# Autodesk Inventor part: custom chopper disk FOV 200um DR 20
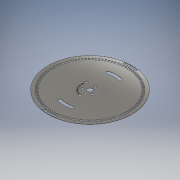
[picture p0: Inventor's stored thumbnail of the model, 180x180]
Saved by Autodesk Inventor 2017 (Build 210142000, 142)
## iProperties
Created: 2016-09
Part Number: custom chopper disk FOV 200um DR 20
Material: Generic
Document SubType Name: Modeling
Designer: Radek
Density: 1 g/cm^3
Appearance: Mirror
Author: Radek
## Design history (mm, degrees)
workplane "Work Plane1"
sketch "Sketch1"
  geometry: L1 (-46.781, 4.422)-(-44.253, 4.183) reference; L2 (-44.362, 2.791)-(-46.897, 2.951) reference; L3 (-46.411, 7.351)-(-43.903, 6.954) reference; L4 (-44.099, 5.571)-(-46.619, 5.889) reference; L5 (-45.858, 10.251)-(-43.38, 9.696) reference; L6 (-43.663, 8.329)-(-46.158, 8.805) reference; L7 (-45.124, 13.11)-(-42.685, 12.401) reference; L8 (-43.054, 11.054)-(-45.514, 11.686) reference; L9 (-44.212, 15.917)-(-41.822, 15.057) reference; L10 (-42.274, 13.736)-(-44.69, 14.521) reference; L11 (-43.125, 18.662)-(-40.794, 17.653) reference; L12 (-41.329, 16.363)-(-43.69, 17.298) reference; L13 (-41.868, 21.333)-(-39.605, 20.18) reference; L14 (-40.22, 18.926)-(-42.518, 20.007) reference; L15 (-40.446, 23.92)-(-38.26, 22.627) reference; L16 (-38.952, 21.414)-(-41.178, 22.638) reference; L17 (-38.865, 26.412)-(-36.764, 24.985) reference; L18 (-37.53, 23.818)-(-39.675, 25.179) reference; L19 (-37.129, 28.801)-(-35.122, 27.244) reference; L20 (-35.961, 26.127)-(-38.016, 27.62) reference; L21 (-35.248, 31.075)-(-33.342, 29.395) reference; L22 (-34.249, 28.333)-(-36.206, 29.953) reference; L23 (-33.227, 33.227)-(-31.431, 31.431) reference; L24 (-32.403, 30.428)-(-34.254, 32.167) reference; L25 (-31.075, 35.248)-(-29.395, 33.342) reference; L26 (-30.428, 32.403)-(-32.167, 34.254) reference; L27 (-28.801, 37.129)-(-27.244, 35.122) reference; L28 (-28.333, 34.249)-(-29.953, 36.206) reference; L29 (-26.412, 38.865)-(-24.985, 36.764) reference; L30 (-26.127, 35.961)-(-27.62, 38.016) reference; L31 (-23.92, 40.446)-(-22.627, 38.26) reference; L32 (-23.818, 37.53)-(-25.179, 39.675) reference; L33 (-21.333, 41.868)-(-20.18, 39.605) reference; L34 (-21.414, 38.952)-(-22.638, 41.178) reference; L35 (-18.662, 43.125)-(-17.653, 40.794) reference; L36 (-18.926, 40.22)-(-20.007, 42.518) reference; L37 (-15.917, 44.212)-(-15.057, 41.822) reference; L38 (-16.363, 41.329)-(-17.298, 43.69) reference; L39 (-13.11, 45.124)-(-12.401, 42.685) reference; L40 (-13.736, 42.274)-(-14.521, 44.69) reference; L41 (-10.251, 45.858)-(-9.696, 43.38) reference; L42 (-11.054, 43.054)-(-11.686, 45.514) reference; L43 (-7.351, 46.411)-(-6.954, 43.903) reference; L44 (-8.329, 43.663)-(-8.805, 46.158) reference; L45 (-4.422, 46.781)-(-4.183, 44.253) reference; L46 (-5.571, 44.099)-(-5.889, 46.619) reference; L47 (-1.476, 46.967)-(-1.396, 44.428) reference; L48 (-2.791, 44.362)-(-2.951, 46.897) reference; L49 (1.476, 46.967)-(1.396, 44.428) reference; L50 (0, 44.45)-(0, 46.99) reference; L51 (4.422, 46.781)-(4.183, 44.253) reference; L52 (2.791, 44.362)-(2.951, 46.897) reference; L53 (7.351, 46.411)-(6.954, 43.903) reference; L54 (5.571, 44.099)-(5.889, 46.619) reference; L55 (10.251, 45.858)-(9.696, 43.38) reference; L56 (8.329, 43.663)-(8.805, 46.158) reference; L57 (13.11, 45.124)-(12.401, 42.685) reference; L58 (11.054, 43.054)-(11.686, 45.514) reference; L59 (15.917, 44.212)-(15.057, 41.822) reference; L60 (13.736, 42.274)-(14.521, 44.69) reference; L61 (18.662, 43.125)-(17.653, 40.794) reference; L62 (16.363, 41.329)-(17.298, 43.69) reference; L63 (21.333, 41.868)-(20.18, 39.605) reference; L64 (18.926, 40.22)-(20.007, 42.518) reference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; C1 r 50.8 at (0, 0) reference; C2 r 2.984 at (0, 0) reference; C3 r 1.524 at (0, 6.553) reference; C4 r 1.524 at (10.339, 5.969) reference; C5 r 2.984 at (0, 0) reference; C6 r 1.524 at (0, -11.938) reference; C7 r 1.524 at (-5.675, -3.277) reference; C8 r 1.524 at (-10.339, 5.969) reference; C9 r 1.524 at (5.675, -3.277) reference; C10 r 50.8 at (0, 0) reference; C11 r 1.524 at (-5.675, -3.277) reference; C12 r 1.524 at (-10.339, 5.969) reference; C13 r 1.524 at (0, 6.553) reference; C14 r 1.524 at (10.339, 5.969) reference; C15 r 1.524 at (5.675, -3.277) reference; C16 r 1.524 at (0, -11.938) reference; C17 r 2.984 at (0, 0) reference; A1 r 17.081 centre (0, 0) between (0, -17.081) and (17.081, 0) reference; A2 r 17.081 centre (0, 0) between (0, 17.081) and (-17.081, 0) reference; A3 r 43.18 centre (0, 0) between (0, 43.18) and (-43.18, 0) reference; A4 r 43.18 centre (0, 0) between (0, -43.18) and (43.18, 0) reference; A5 r 44.45 centre (0, 0) between (-44.253, 4.183) and (-44.362, 2.791) reference; A6 r 46.99 centre (0, 0) between (-46.781, 4.422) and (-46.897, 2.951) reference; A7 r 44.45 centre (0, 0) between (-43.903, 6.954) and (-44.099, 5.571) reference; A8 r 46.99 centre (0, 0) between (-46.411, 7.351) and (-46.619, 5.889) reference; A9 r 44.45 centre (0, 0) between (-43.38, 9.696) and (-43.663, 8.329) reference; A10 r 46.99 centre (0, 0) between (-45.858, 10.251) and (-46.158, 8.805) reference; A11 r 44.45 centre (0, 0) between (-42.685, 12.401) and (-43.054, 11.054) reference; A12 r 46.99 centre (0, 0) between (-45.124, 13.11) and (-45.514, 11.686) reference; A13 r 44.45 centre (0, 0) between (-41.822, 15.057) and (-42.274, 13.736) reference; A14 r 46.99 centre (0, 0) between (-44.212, 15.917) and (-44.69, 14.521) reference; A15 r 44.45 centre (0, 0) between (-40.794, 17.653) and (-41.329, 16.363) reference; A16 r 46.99 centre (0, 0) between (-43.125, 18.662) and (-43.69, 17.298) reference; A17 r 44.45 centre (0, 0) between (-39.605, 20.18) and (-40.22, 18.926) reference; A18 r 46.99 centre (0, 0) between (-41.868, 21.333) and (-42.518, 20.007) reference; A19 r 44.45 centre (0, 0) between (-38.26, 22.627) and (-38.952, 21.414) reference; A20 r 46.99 centre (0, 0) between (-40.446, 23.92) and (-41.178, 22.638) reference; A21 r 44.45 centre (0, 0) between (-36.764, 24.985) and (-37.53, 23.818) reference; A22 r 46.99 centre (0, 0) between (-38.865, 26.412) and (-39.675, 25.179) reference; A23 r 44.45 centre (0, 0) between (-35.122, 27.244) and (-35.961, 26.127) reference; A24 r 46.99 centre (0, 0) between (-37.129, 28.801) and (-38.016, 27.62) reference; A25 r 44.45 centre (0, 0) between (-33.342, 29.395) and (-34.249, 28.333) reference; A26 r 46.99 centre (0, 0) between (-35.248, 31.075) and (-36.206, 29.953) reference; A27 r 44.45 centre (0, 0) between (-31.431, 31.431) and (-32.403, 30.428) reference; A28 r 46.99 centre (0, 0) between (-33.227, 33.227) and (-34.254, 32.167) reference; A29 r 44.45 centre (0, 0) between (-29.395, 33.342) and (-30.428, 32.403) reference; A30 r 46.99 centre (0, 0) between (-31.075, 35.248) and (-32.167, 34.254) reference; A31 r 44.45 centre (0, 0) between (-27.244, 35.122) and (-28.333, 34.249) reference; A32 r 46.99 centre (0, 0) between (-28.801, 37.129) and (-29.953, 36.206) reference; A33 r 44.45 centre (0, 0) between (-24.985, 36.764) and (-26.127, 35.961) reference; A34 r 46.99 centre (0, 0) between (-26.412, 38.865) and (-27.62, 38.016) reference; A35 r 44.45 centre (0, 0) between (-22.627, 38.26) and (-23.818, 37.53) reference; A36 r 46.99 centre (0, 0) between (-23.92, 40.446) and (-25.179, 39.675) reference; A37 r 44.45 centre (0, 0) between (-20.18, 39.605) and (-21.414, 38.952) reference; A38 r 46.99 centre (0, 0) between (-21.333, 41.868) and (-22.638, 41.178) reference; A39 r 44.45 centre (0, 0) between (-17.653, 40.794) and (-18.926, 40.22) reference; A40 r 46.99 centre (0, 0) between (-18.662, 43.125) and (-20.007, 42.518) reference; A41 r 44.45 centre (0, 0) between (-15.057, 41.822) and (-16.363, 41.329) reference; A42 r 46.99 centre (0, 0) between (-15.917, 44.212) and (-17.298, 43.69) reference; A43 r 44.45 centre (0, 0) between (-12.401, 42.685) and (-13.736, 42.274) reference; A44 r 46.99 centre (0, 0) between (-13.11, 45.124) and (-14.521, 44.69) reference; A45 r 44.45 centre (0, 0) between (-9.696, 43.38) and (-11.054, 43.054) reference; A46 r 46.99 centre (0, 0) between (-10.251, 45.858) and (-11.686, 45.514) reference; A47 r 44.45 centre (0, 0) between (-6.954, 43.903) and (-8.329, 43.663) reference; A48 r 46.99 centre (0, 0) between (-7.351, 46.411) and (-8.805, 46.158) reference; A49 r 44.45 centre (0, 0) between (-4.183, 44.253) and (-5.571, 44.099) reference; A50 r 46.99 centre (0, 0) between (-4.422, 46.781) and (-5.889, 46.619) reference; A51 r 44.45 centre (0, 0) between (-1.396, 44.428) and (-2.791, 44.362) reference; A52 r 46.99 centre (0, 0) between (-1.476, 46.967) and (-2.951, 46.897) reference; A53 r 44.45 centre (0, 0) between (1.396, 44.428) and (0, 44.45) reference; A54 r 46.99 centre (0, 0) between (1.476, 46.967) and (0, 46.99) reference; A55 r 44.45 centre (0, 0) between (4.183, 44.253) and (2.791, 44.362) reference; A56 r 46.99 centre (0, 0) between (4.422, 46.781) and (2.951, 46.897) reference; A57 r 44.45 centre (0, 0) between (6.954, 43.903) and (5.571, 44.099) reference; A58 r 46.99 centre (0, 0) between (7.351, 46.411) and (5.889, 46.619) reference; A59 r 44.45 centre (0, 0) between (9.696, 43.38) and (8.329, 43.663) reference; A60 r 46.99 centre (0, 0) between (10.251, 45.858) and (8.805, 46.158) reference; A61 r 44.45 centre (0, 0) between (12.401, 42.685) and (11.054, 43.054) reference; A62 r 46.99 centre (0, 0) between (13.11, 45.124) and (11.686, 45.514) reference; A63 r 44.45 centre (0, 0) between (15.057, 41.822) and (13.736, 42.274) reference; A64 r 46.99 centre (0, 0) between (15.917, 44.212) and (14.521, 44.69) reference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; 1 further point
  constraints: 8 end point, 2 collinear, 1 parallel
extrude "Extrusion2" new body sketch "Sketch1" distance "d2" = 0.254; taper "d3" = 0 deg
sketch "Sketch2"
  geometry: L1 (-46.781, 4.422)-(-44.253, 4.183) reference; L2 (-44.362, 2.791)-(-46.897, 2.951) reference; L3 (-46.411, 7.351)-(-43.903, 6.954) reference; L4 (-44.099, 5.571)-(-46.619, 5.889) reference; L5 (-45.858, 10.251)-(-43.38, 9.696) reference; L6 (-43.663, 8.329)-(-46.158, 8.805) reference; L7 (-45.124, 13.11)-(-42.685, 12.401) reference; L8 (-43.054, 11.054)-(-45.514, 11.686) reference; L9 (-44.212, 15.917)-(-41.822, 15.057) reference; L10 (-42.274, 13.736)-(-44.69, 14.521) reference; L11 (-43.125, 18.662)-(-40.794, 17.653) reference; L12 (-41.329, 16.363)-(-43.69, 17.298) reference; L13 (-41.868, 21.333)-(-39.605, 20.18) reference; L14 (-40.22, 18.926)-(-42.518, 20.007) reference; L15 (-40.446, 23.92)-(-38.26, 22.627) reference; L16 (-38.952, 21.414)-(-41.178, 22.638) reference; L17 (-38.865, 26.412)-(-36.764, 24.985) reference; L18 (-37.53, 23.818)-(-39.675, 25.179) reference; L19 (-37.129, 28.801)-(-35.122, 27.244) reference; L20 (-35.961, 26.127)-(-38.016, 27.62) reference; L21 (-35.248, 31.075)-(-33.342, 29.395) reference; L22 (-34.249, 28.333)-(-36.206, 29.953) reference; L23 (-33.227, 33.227)-(-31.431, 31.431) reference; L24 (-32.403, 30.428)-(-34.254, 32.167) reference; L25 (-31.075, 35.248)-(-29.395, 33.342) reference; L26 (-30.428, 32.403)-(-32.167, 34.254) reference; L27 (-28.801, 37.129)-(-27.244, 35.122) reference; L28 (-28.333, 34.249)-(-29.953, 36.206) reference; L29 (-26.412, 38.865)-(-24.985, 36.764) reference; L30 (-26.127, 35.961)-(-27.62, 38.016) reference; L31 (-23.92, 40.446)-(-22.627, 38.26) reference; L32 (-23.818, 37.53)-(-25.179, 39.675) reference; L33 (-21.333, 41.868)-(-20.18, 39.605) reference; L34 (-21.414, 38.952)-(-22.638, 41.178) reference; L35 (-18.662, 43.125)-(-17.653, 40.794) reference; L36 (-18.926, 40.22)-(-20.007, 42.518) reference; L37 (-15.917, 44.212)-(-15.057, 41.822) reference; L38 (-16.363, 41.329)-(-17.298, 43.69) reference; L39 (-13.11, 45.124)-(-12.401, 42.685) reference; L40 (-13.736, 42.274)-(-14.521, 44.69) reference; L41 (-10.251, 45.858)-(-9.696, 43.38) reference; L42 (-11.054, 43.054)-(-11.686, 45.514) reference; L43 (-7.351, 46.411)-(-6.954, 43.903) reference; L44 (-8.329, 43.663)-(-8.805, 46.158) reference; L45 (-4.422, 46.781)-(-4.183, 44.253) reference; L46 (-5.571, 44.099)-(-5.889, 46.619) reference; L47 (-1.476, 46.967)-(-1.396, 44.428) reference; L48 (-2.791, 44.362)-(-2.951, 46.897) reference; L49 (1.476, 46.967)-(1.396, 44.428) reference; L50 (0, 44.45)-(0, 46.99) reference; L51 (4.422, 46.781)-(4.183, 44.253) reference; L52 (2.791, 44.362)-(2.951, 46.897) reference; L53 (7.351, 46.411)-(6.954, 43.903) reference; L54 (5.571, 44.099)-(5.889, 46.619) reference; L55 (10.251, 45.858)-(9.696, 43.38) reference; L56 (8.329, 43.663)-(8.805, 46.158) reference; L57 (13.11, 45.124)-(12.401, 42.685) reference; L58 (11.054, 43.054)-(11.686, 45.514) reference; L59 (15.917, 44.212)-(15.057, 41.822) reference; L60 (13.736, 42.274)-(14.521, 44.69) reference; L61 (18.662, 43.125)-(17.653, 40.794) reference; L62 (16.363, 41.329)-(17.298, 43.69) reference; L63 (21.333, 41.868)-(20.18, 39.605) reference; L64 (18.926, 40.22)-(20.007, 42.518) reference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; C1 r 50.8 at (0, 0) reference; C2 r 1.524 at (-5.675, -3.277) reference; C3 r 1.524 at (-10.339, 5.969) reference; C4 r 1.524 at (0, 6.553) reference; C5 r 1.524 at (10.339, 5.969) reference; C6 r 1.524 at (5.675, -3.277) reference; C7 r 1.524 at (0, -11.938) reference; C8 r 2.984 at (0, 0) reference; A1 r 44.45 centre (0, 0) between (-44.253, 4.183) and (-44.362, 2.791) reference; A2 r 46.99 centre (0, 0) between (-46.781, 4.422) and (-46.897, 2.951) reference; A3 r 44.45 centre (0, 0) between (-43.903, 6.954) and (-44.099, 5.571) reference; A4 r 46.99 centre (0, 0) between (-46.411, 7.351) and (-46.619, 5.889) reference; A5 r 44.45 centre (0, 0) between (-43.38, 9.696) and (-43.663, 8.329) reference; A6 r 46.99 centre (0, 0) between (-45.858, 10.251) and (-46.158, 8.805) reference; A7 r 44.45 centre (0, 0) between (-42.685, 12.401) and (-43.054, 11.054) reference; A8 r 46.99 centre (0, 0) between (-45.124, 13.11) and (-45.514, 11.686) reference; A9 r 44.45 centre (0, 0) between (-41.822, 15.057) and (-42.274, 13.736) reference; A10 r 46.99 centre (0, 0) between (-44.212, 15.917) and (-44.69, 14.521) reference; A11 r 44.45 centre (0, 0) between (-40.794, 17.653) and (-41.329, 16.363) reference; A12 r 46.99 centre (0, 0) between (-43.125, 18.662) and (-43.69, 17.298) reference; A13 r 44.45 centre (0, 0) between (-39.605, 20.18) and (-40.22, 18.926) reference; A14 r 46.99 centre (0, 0) between (-41.868, 21.333) and (-42.518, 20.007) reference; A15 r 44.45 centre (0, 0) between (-38.26, 22.627) and (-38.952, 21.414) reference; A16 r 46.99 centre (0, 0) between (-40.446, 23.92) and (-41.178, 22.638) reference; A17 r 44.45 centre (0, 0) between (-36.764, 24.985) and (-37.53, 23.818) reference; A18 r 46.99 centre (0, 0) between (-38.865, 26.412) and (-39.675, 25.179) reference; A19 r 44.45 centre (0, 0) between (-35.122, 27.244) and (-35.961, 26.127) reference; A20 r 46.99 centre (0, 0) between (-37.129, 28.801) and (-38.016, 27.62) reference; A21 r 44.45 centre (0, 0) between (-33.342, 29.395) and (-34.249, 28.333) reference; A22 r 46.99 centre (0, 0) between (-35.248, 31.075) and (-36.206, 29.953) reference; A23 r 44.45 centre (0, 0) between (-31.431, 31.431) and (-32.403, 30.428) reference; A24 r 46.99 centre (0, 0) between (-33.227, 33.227) and (-34.254, 32.167) reference; A25 r 44.45 centre (0, 0) between (-29.395, 33.342) and (-30.428, 32.403) reference; A26 r 46.99 centre (0, 0) between (-31.075, 35.248) and (-32.167, 34.254) reference; A27 r 44.45 centre (0, 0) between (-27.244, 35.122) and (-28.333, 34.249) reference; A28 r 46.99 centre (0, 0) between (-28.801, 37.129) and (-29.953, 36.206) reference; A29 r 44.45 centre (0, 0) between (-24.985, 36.764) and (-26.127, 35.961) reference; A30 r 46.99 centre (0, 0) between (-26.412, 38.865) and (-27.62, 38.016) reference; A31 r 44.45 centre (0, 0) between (-22.627, 38.26) and (-23.818, 37.53) reference; A32 r 46.99 centre (0, 0) between (-23.92, 40.446) and (-25.179, 39.675) reference; A33 r 44.45 centre (0, 0) between (-20.18, 39.605) and (-21.414, 38.952) reference; A34 r 46.99 centre (0, 0) between (-21.333, 41.868) and (-22.638, 41.178) reference; A35 r 44.45 centre (0, 0) between (-17.653, 40.794) and (-18.926, 40.22) reference; A36 r 46.99 centre (0, 0) between (-18.662, 43.125) and (-20.007, 42.518) reference; A37 r 44.45 centre (0, 0) between (-15.057, 41.822) and (-16.363, 41.329) reference; A38 r 46.99 centre (0, 0) between (-15.917, 44.212) and (-17.298, 43.69) reference; A39 r 44.45 centre (0, 0) between (-12.401, 42.685) and (-13.736, 42.274) reference; A40 r 46.99 centre (0, 0) between (-13.11, 45.124) and (-14.521, 44.69) reference; A41 r 44.45 centre (0, 0) between (-9.696, 43.38) and (-11.054, 43.054) reference; A42 r 46.99 centre (0, 0) between (-10.251, 45.858) and (-11.686, 45.514) reference; A43 r 44.45 centre (0, 0) between (-6.954, 43.903) and (-8.329, 43.663) reference; A44 r 46.99 centre (0, 0) between (-7.351, 46.411) and (-8.805, 46.158) reference; A45 r 44.45 centre (0, 0) between (-4.183, 44.253) and (-5.571, 44.099) reference; A46 r 46.99 centre (0, 0) between (-4.422, 46.781) and (-5.889, 46.619) reference; A47 r 44.45 centre (0, 0) between (-1.396, 44.428) and (-2.791, 44.362) reference; A48 r 46.99 centre (0, 0) between (-1.476, 46.967) and (-2.951, 46.897) reference; A49 r 44.45 centre (0, 0) between (1.396, 44.428) and (0, 44.45) reference; A50 r 46.99 centre (0, 0) between (1.476, 46.967) and (0, 46.99) reference; A51 r 44.45 centre (0, 0) between (4.183, 44.253) and (2.791, 44.362) reference; A52 r 46.99 centre (0, 0) between (4.422, 46.781) and (2.951, 46.897) reference; A53 r 44.45 centre (0, 0) between (6.954, 43.903) and (5.571, 44.099) reference; A54 r 46.99 centre (0, 0) between (7.351, 46.411) and (5.889, 46.619) reference; A55 r 44.45 centre (0, 0) between (9.696, 43.38) and (8.329, 43.663) reference; A56 r 46.99 centre (0, 0) between (10.251, 45.858) and (8.805, 46.158) reference; A57 r 44.45 centre (0, 0) between (12.401, 42.685) and (11.054, 43.054) reference; A58 r 46.99 centre (0, 0) between (13.11, 45.124) and (11.686, 45.514) reference; A59 r 44.45 centre (0, 0) between (15.057, 41.822) and (13.736, 42.274) reference; A60 r 46.99 centre (0, 0) between (15.917, 44.212) and (14.521, 44.69) reference; A61 r 44.45 centre (0, 0) between (17.653, 40.794) and (16.363, 41.329) reference; A62 r 46.99 centre (0, 0) between (18.662, 43.125) and (17.298, 43.69) reference; A63 r 44.45 centre (0, 0) between (20.18, 39.605) and (18.926, 40.22) reference; A64 r 46.99 centre (0, 0) between (21.333, 41.868) and (20.007, 42.518) reference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; 1 further point
  constraints: 8 end point, 1 collinear
extrude "Extrusion3" cut sketch "Sketch2" stored distance "d4" = 0.254; taper "d5" = 0 deg
sketch "Sketch3" dims "d20" = 1.32222 (= 0.5 x holediameter), "d21" = 1.8699 (= 1.41421 x d20)
  geometry: L1 (-10.339, 5.969)-(10.339, 5.969); L2 (0, 0)-(50.8, 0); L3 (0, 44.45)-(0, 46.99) reference; L4 (0, 0)-(0, 50.8); L5 (0, 30)-(0, 28.13); L6 (0, 50.165)-(0, 48.26) reference; L7 (-48.26, 0)-(-50.165, 0) reference; L8 (0, 0)-(-3.071, -13.883); L9 (0, 50.8)-(0, 50.165); L10 (7.281, 27.172)-(8.273, 30.777); L11 (-7.281, 27.172)-(-8.273, 30.777); C1 r 2.984 at (0, 0) reference; C2 r 15.25 at (0, 0); C3 r 1.524 at (-10.339, 5.969) reference; C4 r 1.524 at (0, -11.938) reference; C5 r 1.524 at (10.339, 5.969) reference; C6 r 1.524 at (-5.675, -3.277) reference; C7 r 1.524 at (5.675, -3.277) reference; A1 r 50.8 centre (0, 0) between (50.8, 0) and (0, 50.8) reference; A2 r 48.26 centre (0, 0) between (0, 48.26) and (-48.26, 0) reference; A3 r 50.165 centre (0, 0) between (0, 50.165) and (-50.165, 0) reference; A4 r 50.165 centre (0, 0) between (-20.154, -45.939) and (22.037, -45.066); A5 r 48.26 centre (0, 0) between (-19.033, -44.348) and (20.956, -43.472); 3 further points; 3 other entities
  constraints: 16 end point, 8 point on circle, 3 centre point, 3 coincident, 2 vertical, 1 collinear, 1 horizontal, 1 parallel, 1 point on line, 1 vertical alignment, 19 other
  dimensions: "d9" = 30.5 diameter of C2; "d18" = 0 distance between parallel lines of L4 L5; "d19" = 30 distance of point (0, 0) L5.start (= offaxis); "d24" = 15 deg dimension on point (0, 0) L5.start point (-7.765, 28.978) (= 0.5 x angle); "d28" = 15 deg dimension on point (0, 0) point (7.765, 28.978) L5.start (= 0.5 x angle); "d32" = 0.635 distance of L4.end L6.start (derived)
extrude "Extrusion7" cut sketch "Sketch3" stored distance "d40" = 10; taper "d41" = 0 deg
sketch "Sketch4"
  geometry: L1 (-8.273, 30.777)-(-7.281, 27.172) reference; L2 (7.281, 27.172)-(8.273, 30.777) reference; L3 (8.273, 30.777)-(7.281, 27.172) reference; L4 (-7.281, 27.172)-(-8.273, 30.777) reference; L5 (-7.281, 27.172)-(-8.273, 30.777); L6 (7.281, 27.172)-(8.273, 30.777); C1 r 2.984 at (0, 0) reference; C2 r 50.8 at (0, 0) reference; A1 r 28.13 centre (0, 0) between (7.281, 27.172) and (-7.281, 27.172); A2 r 31.87 centre (0, 0) between (8.273, 30.777) and (-8.273, 30.777); 3 further points; 2 other entities
  constraints: 4 end point, 4 point on circle, 2 centre point, 2 coincident, 2 collinear, 2 other
extrude "Extrusion8" cut sketch "Sketch4" stored distance "d42" = 10; taper "d43" = 0 deg
sketch "Sketch5"
  geometry: L1 (0, 0)-(-7.947, 50.175); L2 (0, 0)-(7.947, 50.175); L3 (7.524, 47.508)-(7.837, 49.483); L4 (-7.524, 47.508)-(-7.837, 49.483); L5 (6.954, 43.903)-(7.351, 46.411) reference; L6 (4.422, 46.781)-(4.183, 44.253) reference; L7 (7.351, 46.411)-(6.954, 43.903) reference; C1 r 2.984 at (0, 0) reference; A1 r 50.8 centre (0, 0) between (-7.947, 50.175) and (7.947, 50.175) reference; A2 r 28.13 centre (0, 0) between (7.281, 27.172) and (-7.281, 27.172) reference; A3 r 31.87 centre (0, 0) between (8.273, 30.777) and (-8.273, 30.777) reference; A4 r 48.1 centre (0, 0) between (7.524, 47.508) and (-7.524, 47.508); A5 r 50.1 centre (0, 0) between (7.837, 49.483) and (-7.837, 49.483); 4 further points; 2 other entities
  constraints: 8 end point, 6 point on circle, 3 point on line, 2 centre point, 2 coincident, 2 collinear, 1 midpoint, 8 other
  dimensions: "d44" = 0.7 radial gap between concentric circles of A1 A5; "d45" = 2 radial gap between concentric circles of A5 A4; "d53" = 18 deg angle of L1 L2
extrude "Extrusion9" cut sketch "Sketch5" stored distance "d46" = 10; taper "d47" = 0 deg
pattern_circular "Circular Pattern3" dims angle "d49" = 360 deg
sketch "Sketch6"
  geometry: L1 (28.13, 0)-(27.172, 0) reference; L2 (30.777, 0)-(31.87, 0) reference; L3 (27.172, -0.254)-(28.13, -0.254) reference; L4 (31.87, -0.254)-(30.777, -0.254) reference; L5 (-50.8, 0)-(50.8, 0) reference; L6 (-50.8, -0.254)-(50.8, -0.254) reference; L7 (28.13, 0)-(31.87, 0); L8 (28.13, -0.254)-(31.87, -0.254); L9 (30, -0.254)-(30, 0); L10 (30, -0.127)-(32.935, -3.062); 1 further point
  constraints: 8 end point, 3 midpoint, 1 collinear, 1 parallel
  dimensions: "d51" = 135 deg angle of L10 L9
workaxis "Work Axis1"
workplane "Work Plane3"
  workplane "Work Plane2"
sketch "Sketch7"
  geometry: L1 (0, -11.938)-(-10.339, 5.969); L2 (0, -11.938)-(4.086, -9.579); C1 r 1.524 at (0, -11.938) reference; C2 r 1.524 at (-10.339, 5.969) reference; C3 r 2.984 at (0, 0) reference; 4 further points
  constraints: 4 end point, 2 coincident, 1 perpendicular, 4 other
extrude "Extrusion11" cut sketch "Sketch7" stored distance "d57" = 10; taper "d58" = 0 deg
body "Solid2"
pattern_circular "Circular Pattern1" dims angle "d7" = 360 deg
node "Reference1"
node "Reference2"
node "Reference3"
node "Reference4"
node "Reference5"
node "Reference6"
node "Reference7"
node "Reference8"
node "Reference9"
node "Reference10"
node "Reference11"
node "Reference12"
node "Reference13"
node "Reference14"
node "Reference15"
node "Reference16"
node "Reference17"
node "Reference18"
node "Reference19"
other parameters: "d12" = 1.72222 (computed from ftube, FOV), "FOV" = 0.2 [user parameter; used in 2 equation terms], "dutycycle" = 1.94725 (computed from holelength, offaxis) [user parameter], "offaxis" = 30 [user parameter; used in 4 equation terms], "angle" = 30 deg (computed from holediameter, holelength, offaxis) [user parameter; used in 2 equation terms], "holelength" = 18.35241 (computed from dutyratio, offaxis, holediameter) [user parameter; used in 2 equation terms], "holediameter" = 2.64444 (computed from FOV, ftube) [user parameter; used in 3 equation terms], "dutyratio" = 2 [user parameter; used in 1 equation term], "d52" = 45 deg
